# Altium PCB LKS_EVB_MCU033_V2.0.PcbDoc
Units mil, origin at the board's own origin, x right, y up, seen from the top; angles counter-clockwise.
Board outline 2625 x 1560 mil, 2 copper layers (Top Layer, Bottom Layer); 25 components, 32 nets, 123 pads, 18 vias.
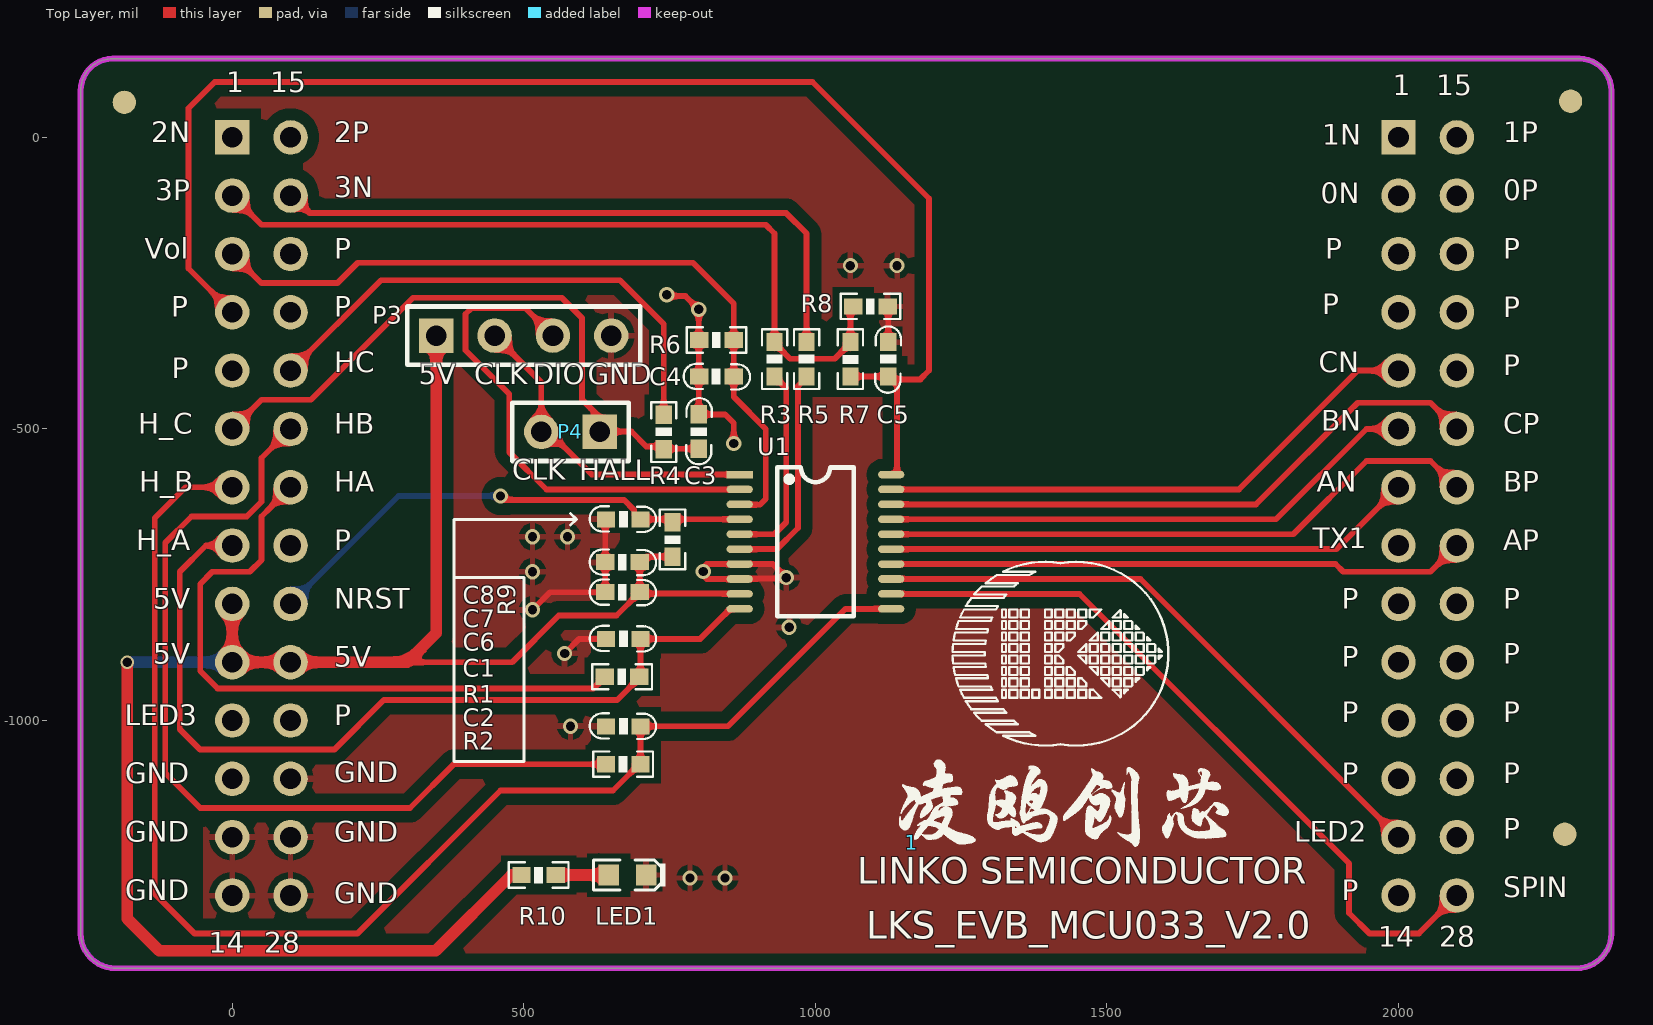
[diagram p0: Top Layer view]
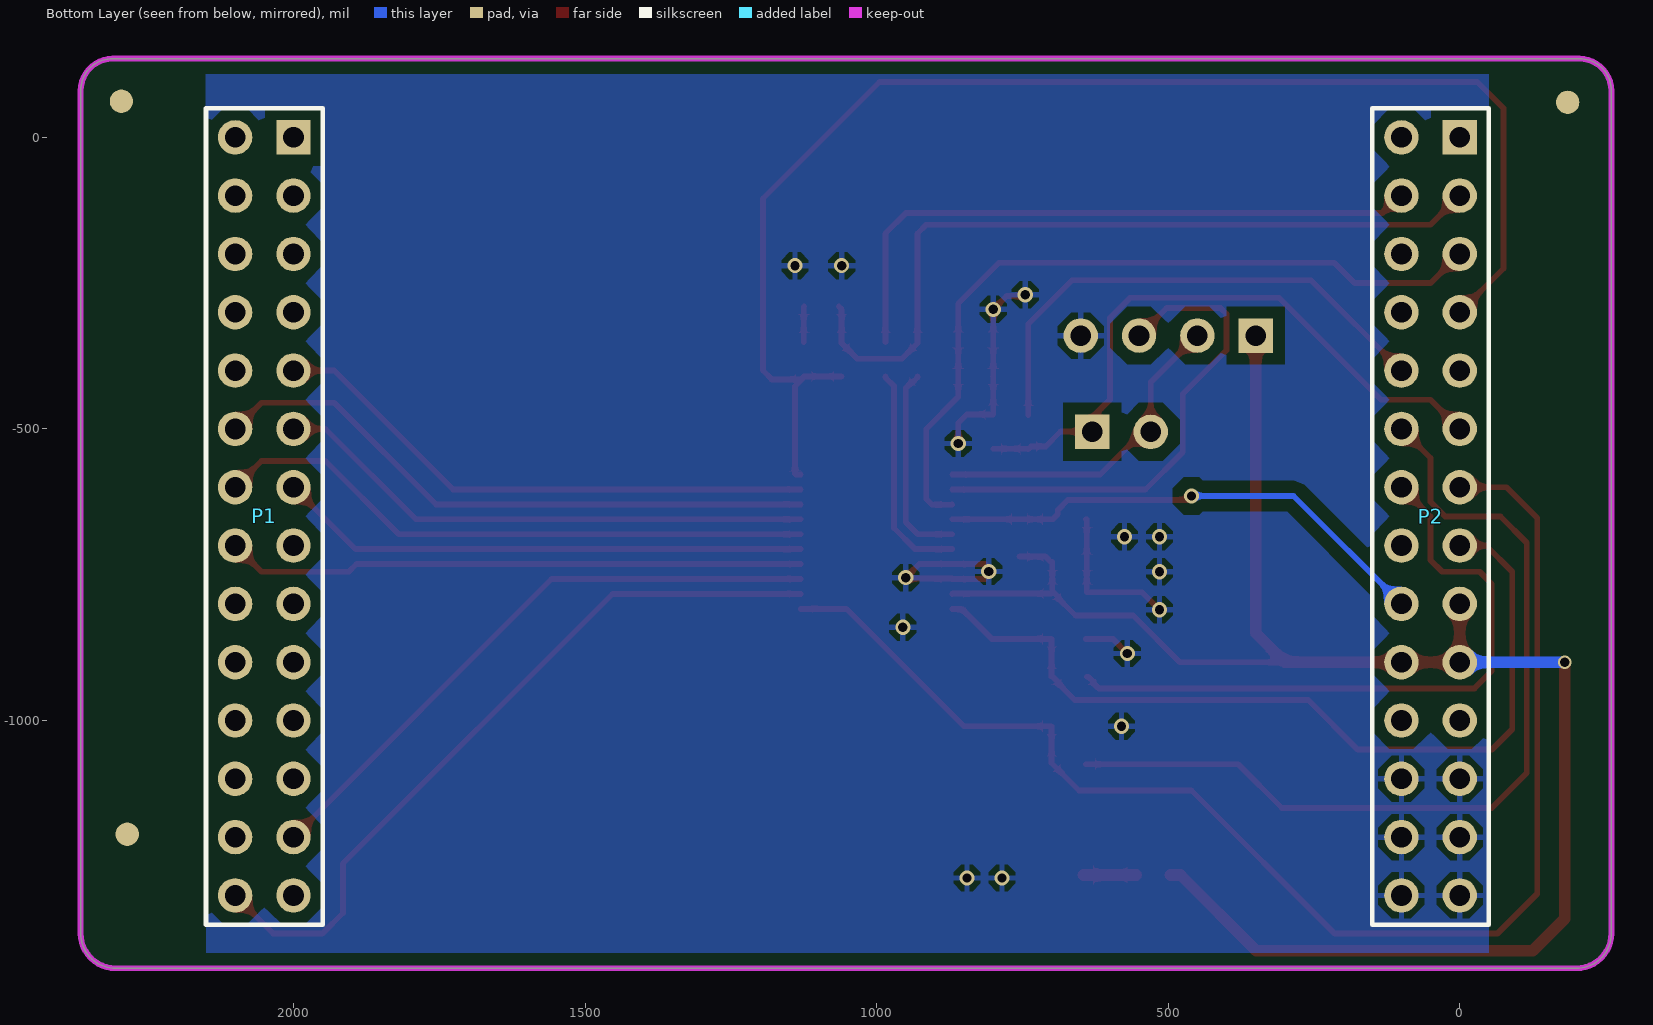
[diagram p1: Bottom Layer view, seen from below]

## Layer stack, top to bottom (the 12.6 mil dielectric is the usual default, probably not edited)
Top Solder: solder mask 0.4, Solder Resist, Dk 3.5
Top Layer: signal copper 1.4
Dielectric 1: dielectric 12.6, FR-4, Dk 4.8
Bottom Layer: signal copper 1.4
Bottom Solder: solder mask 0.4, Solder Resist, Dk 3.5

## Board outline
-260,-1365 ccw(c-200,-1365) -200,-1425 2305,-1425 ccw(c2305,-1365) 2365,-1365 2365,80 ccw(c2310,80) 2310,135 -205,135 ccw(c-205,80) -260,80
cut-out: -2580,-3405 -2570,-3405 -2570,-3395 -2580,-3395

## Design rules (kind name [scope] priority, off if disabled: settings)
Clearance Clearance_2 [InPolygon] p1: gap=20 ignorepadtopadclearanceinfootprint=FALSE
Clearance Clearance_1 [InNet('+5V')] p2: gap=10 ignorepadtopadclearanceinfootprint=FALSE
Clearance [All] p3: gap=7.87 ignorepadtopadclearanceinfootprint=FALSE
ComponentClearance [All] p1: gap=0 collisioncheckmode=3 verticalgap=0 showdistances=FALSE
MinimumSolderMaskSliver [All] p1: minsoldermaskwidth=0
PolygonConnect [All] p1: connectstyle=Relief reliefconductorwidth=10 reliefentries=4 polygonreliefangle="90 Angle" airgapwidth=10
RoutingVias [All] p1: holewidth=28 width=50 viastyle="Through Hole" minholewidth=28 minwidth=50 maxholewidth=28 maxwidth=50
SilkToSilkClearance [All] p1: silktosilkclearance=5
SilkToSolderMaskClearance [IsPad] p1: minsilkscreentomaskgap=5 clearancetoexposedcopper=TRUE
SolderMaskExpansion [All] p1: expansion=4 istentingtop=FALSE
Width [All] p1: maxlimit=100 minlimit=1 preferedwidth=10
26 further rules are at their usual default settings.

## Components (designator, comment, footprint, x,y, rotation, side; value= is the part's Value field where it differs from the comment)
1 "LKS_sign" LKS_LOGO2 1165,-1210 r0 top
C1 "10nF/16V" 0603C 700,-860 r180 top
C2 "10nF/16V" 0603C 700,-1010 r180 top
C3 "10nF/16V" 0603C 800,-534.06 r90 top
C4 "100nF/50V" 0603C 800.94,-410 r0 top
C5 "1nF/50V" 0603C 1125,-350.94 r270 top
C6 "10uF/10V" 0603C 639.76,-780 r0 top
C7 "100nF/50V" 0603C 639.76,-728.43 r0 top
C8 "100nF/50V" 0603C 700,-655 r180 top
LED1 "LED" 0603D 677.82,-1265 r0 top
P1 "Header 14X2A" HDR2X14_CEN 2000,0 r270 bottom
P2 "Header 14X2A" HDR2X14_CEN 0,0 r270 bottom
P3 "Header 4" HDR1X4 350,-340 r0 top
P4 "Header 2" HDR1X2 630,-505 r180 top
R1 "2K" 0603R 638.98,-925 r0 top value=K
R2 "2K" 0603R 640.94,-1075 r0 top value=K
R3 "1K1%" 0603R 930,-350.94 r270 top value=K
R4 "2K" 0603R 740,-475.94 r270 top value=K
R5 "1K1%" 0603R 985,-350.94 r270 top value=K
R6 "1K1%" 0603R 800.94,-347.5 r0 top value=K
R7 "1K1%" 0603R 1060,-410 r90 top value=K
R8 "10R" 0603R 1065,-290 r0 top value=K
R9 "20K1%" 0603R 755,-719.06 r90 top value=K
R10 "3.3K" 0603R 495.94,-1265 r0 top value=330
U1 "LKS033" TSSOP-20 845.16,-561.23 r0 top

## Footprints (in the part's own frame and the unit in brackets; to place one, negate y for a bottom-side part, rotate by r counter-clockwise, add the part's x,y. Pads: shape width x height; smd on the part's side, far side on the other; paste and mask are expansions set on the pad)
0603C [mm]
  rect 0.8x0.7 smd: 1(0,0) 2(1.5,0)
  silkscreen extent -0.68,-0.57 2.21,0.55
0603D [mm]
  rect 0.9x0.9 smd: 1(-0.813,0) 2(0.813,0)
  silkscreen extent -1.47,-0.66 1.65,0.66
0603R [mm]
  rect 0.8x0.7 smd: 1(0,0) 2(1.5,0)
  silkscreen extent -0.55,-0.55 2.05,0.55
HDR1X2 [mm] "Connector; Header; 2 Position"
  rect 1.5x1.5 hole 0.9: 1(0,0)
  round 1.5 hole 0.9: 2(2.54,0)
  silkscreen extent -1.27,-1.27 3.81,1.27
HDR1X4 [mm] "Connector; Header; 4 Position"
  rect 1.5x1.5 hole 0.9: 1(0,0)
  round 1.5 hole 0.9: 2(2.54,0) 3(5.08,0) 4(7.62,0)
  silkscreen extent -1.27,-1.27 8.89,1.27
HDR2X14_CEN [mm] "Connector; Header; 14x2 Position"
  rect 1.5x1.5 hole 0.9: 1(0,0)
  round 1.5 hole 0.9: 2(2.54,0) 3(5.08,0) 4(7.62,0) 5(10.16,0) 6(12.7,0) 7(15.24,0) 8(17.78,0) 9(20.32,0) 10(22.86,0) 11(25.4,0) 12(27.94,0) 13(30.48,0) 14(33.02,0) 15(0,-2.54) 16(2.54,-2.54) 17(5.08,-2.54) 18(7.62,-2.54) 19(10.16,-2.54) 20(12.7,-2.54) 21(15.24,-2.54) 22(17.78,-2.54) 23(20.32,-2.54) 24(22.86,-2.54) 25(25.4,-2.54) 26(27.94,-2.54) 27(30.48,-2.54) 28(33.02,-2.54)
  silkscreen extent -1.27,-3.81 34.29,1.27
LKS_LOGO2 [mil] "LOGO?"
  silkscreen extent 70,167 440,482
TSSOP-20 [mm] "6.50x4.40x1.00 e=0.65（蒜米工坊）"
  rect 1.143x0.33 smd: 1(0.635,-0.432)
  oval 1.143x0.33 smd: 2(0.635,-1.082) 3(0.635,-1.732) 4(0.635,-2.382) 5(0.635,-3.032) 6(0.635,-3.682) 7(0.635,-4.332) 8(0.635,-4.982) 9(0.635,-5.632) 10(0.635,-6.282) 11(7.235,-6.282) 12(7.235,-5.632) 13(7.235,-4.982) 14(7.235,-4.332) 15(7.235,-3.682) 16(7.235,-3.032) 17(7.235,-2.382) 18(7.235,-1.732) 19(7.235,-1.082) 20(7.235,-0.432)
  silkscreen extent 2.27,-6.61 5.6,-0.11, body extent 0.73,-6.55 7.14,-0.05, height 1.03

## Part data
C1 C2 C3: library part CAP, "Capacitor"
C4 C5 C6 C7 C8: library part C, "Capacitor"
LED1: "LED_Light"
P1 P2: "Header, 14-Pin, Dual row"
P3: "Header, 4-Pin"
P4: "Header, 2-Pin"
R1 R2 R3 R4 R5 R6 R7 R8 R9 R10: library part Res, "Resistor"
U1: library part LKS32MC033H6S8, "CHIP--TSSOP20"

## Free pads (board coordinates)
  round 40 all layers, no hole: 2(2295,61.86) 3(2285,-1195) 4(-185,60)

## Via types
v1: diameter 26, hole 16, Top Layer to Bottom Layer, 17 vias
v2: diameter 23.62, hole 15.75, Top Layer to Bottom Layer, 1 vias

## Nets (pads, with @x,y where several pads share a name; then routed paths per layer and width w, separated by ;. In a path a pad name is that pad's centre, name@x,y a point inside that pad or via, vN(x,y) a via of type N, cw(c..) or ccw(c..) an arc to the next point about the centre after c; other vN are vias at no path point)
+5V: C6.2 C7.2 P2.9 P2.10 P2.24 P3.1 R9.1 R10.1 U1.9 | length 3087.2
  Top Layer w10: 300,-900 480,-900 560,-820 658.82,-820 688.07,-790.75 688.07,-788.78 696.85,-780 C6.2 ; R9.1 710.16,-719.06 700.79,-728.43 C7.2 C6.2 ; U1.9 869.59,-782.38 701.2,-782.38 C6.2
  Top Layer w20: v2(-180,-900) -180,-1340 -125,-1395 348.98,-1395 478.98,-1265 R10.1 ; P2.9 P2.10 P2.24 300,-900 350,-850 P3.1
  Bottom Layer w20: v2(-180,-900) P2.10
GND: C1.2 C2.2 C3.2 C4.1 C5.1 C6.1 C7.1 C8.2 LED1.2 P2.12 P2.13 P2.14 P2.26 P2.27 P2.28 P3.4 R6.1 R8.2 U1.7 U1.8 | length 1067
  Top Layer w10: v1(515,-810) 545,-780 C6.1 C7.1 639.76,-655 C8.2 ; v1(570,-885) 595,-860 C1.2 ; v1(745,-270) 747.33,-272.33 777.33,-272.33 v1(800,-295) 800,-409.06 C4.1 800,-410.94 C3.2 845,-475 860,-490 v1(860,-525) ; R8.2 1125,-290.95 C5.1 ; v1@807.82,-751.5 v1(807.82,-744.57) 807.82,-737.63 813.68,-731.77 U1.7 926.77,-731.77 v1(950,-755) 948.21,-756.79 870.73,-756.79 U1.8 813.68,-757.36 v1@807.82,-751.5
  other v1: 785,-1270 845,-1270 580,-1010 955,-840 515,-745 515,-685 575,-685 1060,-220 1140,-220
GND0: P2.16 R5.1 | length 1097.9
  Top Layer w10: P2.16 102.97,-100 132.97,-130 950,-130 985,-165 R5.1
HALL_U: C1.1 P2.8 R1.2 U1.10 | length 1492.5
  Top Layer w10: P2.8 -45,-700 -90,-745 -90,-1015 -55,-1050 175,-1050 260,-965 660,-965 689.25,-935.75 689.25,-933.78 R1.2 700,-925 C1.1 802.7,-860 854.15,-808.54 U1.10
HALL_V: C2.1 P2.7 R2.2 U1.11 | length 2357.4
  Top Layer w10: P2.7 -80,-600 -132.87,-652.87 -132.87,-1297.13 -65,-1365 215,-1365 460,-1120 653.03,-1120 700,-1073.03 C2.1 850,-1010 1051.46,-808.54 U1.11
HALL_W: C3.1 P2.6 P4.1 R4.2 | length 1083.3
  Top Layer w10: P2.6 50,-450 135,-450 310,-275 565,-275 600,-310 600,-450 630,-480 654.53,-504.53 684.53,-504.53 710,-530 735,-530 R4.2 740.94,-534.06 C3.1
HU: P2.21 R1.1 | length 1132.6
  Top Layer w10: P2.21 66.99,-633.01 66.99,-633.29 50,-650.28 50,-725 30,-745 -34.14,-745 -55,-765.86 -55,-915 -25,-945 618.98,-945 628.23,-935.75 628.23,-933.78 637.01,-925 R1.1
HV: P2.20 R2.1 | length 1546.6
  Top Layer w10: P2.20 50,-550 50,-625 25,-650 -70,-650 -115,-695 -115,-1090 -55,-1150 305,-1150 380,-1075 R2.1
HW: P2.19 R4.1 | length 891.2
  Top Layer w10: P2.19 255,-245 665,-245 740,-320 R4.1
LED2: P1.13 U1.13 | length 1053.3
  Top Layer w10: U1.13 1557.36,-757.36 P1.13
NetLED1_1: LED1.1 R10.2 | length 90.8
  Top Layer w20: R10.2 LED1.1
NRST: C8.1 P2.23 R9.2 U1.4 | length 867.4
  Top Layer w10: v1(460,-615) 464.33,-615 471.02,-621.69 671.69,-621.69 689.25,-639.25 689.25,-646.22 698.03,-655 755,-655 U1.4
  Bottom Layer w10: P2.23 285,-615 v1(460,-615)
OC: C5.2 P2.4 R7.1 U1.20 | length 2374.5
  Top Layer w10: P2.4 -75,-225 -75,50 -30,95 995,95 1195,-105 1195,-400 1180,-415 1130,-415 C5.2 ; R7.1 C5.2 ; U1.20 1138.62,-578.23 1140,-576.85 1140,-426.97 1125,-411.97 C5.2
OPA1_IN: R5.2 U1.6 | length 381.3
  Top Layer w10: U1.6 933.82,-706.18 970,-670 970,-426.61 975.86,-420.75 976.22,-420.75 985,-411.97 R5.2
OPA1_IP: R3.2 U1.5 | length 347.8
  Top Layer w10: U1.5 929.41,-680.59 950,-660 950,-430 940.75,-420.75 938.78,-420.75 930,-411.97 R3.2
PGND: P2.2 R3.1 R7.2 R8.1 | length 1361.9
  Top Layer w10: P2.2 50,-150 915,-150 930,-165 R3.1 930,-352.91 956.65,-379.57 1033.35,-379.57 1060,-352.91 R7.2 1060,-295 R8.1
PGND0: P1.2
PGND1: P1.1
PGND2: P2.1
SPin: P1.28 U1.12 | length 1292.8
  Top Layer w10: U1.12 1452.95,-782.95 1915,-1245 1915,-1330 1950,-1365 2035,-1365 P1.28
  Bottom Layer w10: P1.28 P1.28@2100,-1295
SWCLK: P3.2 P4.2 U1.1 | length 560.8
  Top Layer w10: P3.2 530,-420 530,-491.61 616.61,-578.23 U1.1
SWDIO: P3.3 U1.2 | length 863.4
  Top Layer w10: P3.3 502.87,-292.87 410,-292.87 400,-302.87 400,-365 475,-440 475,-540 538.82,-603.82 U1.2
UN: P1.7 U1.15 | length 914
  Top Layer w10: U1.15 1893.82,-706.18 P1.7
UP: P1.22 U1.14 | length 994.1
  Top Layer w10: U1.14 1891.77,-731.77 1905,-745 2055,-745 P1.22
UP-: P2.15
VN: P1.6 U1.17 | length 934.2
  Top Layer w10: U1.17 1790,-655 1945,-500 P1.6
Vol_ADC: C4.2 P2.3 R6.2 U1.3 | length 1331.2
  Top Layer w10: P2.3 50,-250 180,-250 215,-215 790,-215 860,-285 R6.2 C4.2 860,-445 915,-500 915,-620 905,-630 870.73,-629.98 U1.3
VP: P1.21 U1.16 | length 1040.7
  Top Layer w10: U1.16 1819.41,-680.59 1945,-555 2055,-555 P1.21
VP-: P1.15
WN: P1.5 U1.19 | length 954.4
  Top Layer w10: U1.19 1726.18,-603.82 1930,-400 P1.5
WP: P1.20 U1.18 | length 1060.9
  Top Layer w10: U1.18 1755.59,-629.41 1930,-455 2055,-455 P1.20
WP-: P1.16
pads on no net: P1.3 P1.4 P1.8 P1.9 P1.10 P1.11 P1.12 P1.14 P1.17 P1.18 P1.19 P1.23 P1.24 P1.25 P1.26 P1.27 P2.5 P2.11 P2.17 P2.18 P2.22 P2.25

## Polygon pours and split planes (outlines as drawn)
GND on Bottom Layer "GND_L02_P000" (solid, remove dead copper, pour order 0): -50,128.77 -50,-1425 2150,-1425 2150,134.58
GND on Top Layer "GND_L01_P005" (solid, remove dead copper, pour order 5): -50,-1425 2150,-1425 2150,135 -50,135

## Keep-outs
Keep-Out Layer:
  the board outline again, w10

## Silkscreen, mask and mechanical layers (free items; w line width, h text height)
Top Overlay:
  drawing of 16 lines, arcs and shapes, not listed
  text "2N" at -138.73,-20 h60
  text "2P" at 175,-20 h60
  text "1P" at 2180,-20 h60
  text "1N" at 1869.55,-25 h60
  text "3N" at 174.94,-115 h60
  text "3P" at -131.62,-120 h60
  text "0P" at 2179.94,-120 h60
  text "0N" at 1866.83,-125 h60
  text "Vol" at -149.61,-220 h60
  text "P" at 175,-220 h60
  text "P" at 1874.54,-220 h60
  text "P" at 2180,-220 h60
  text "P" at 1869.27,-315 h60
  text "P" at -105,-320 h60
  text "P" at 175,-320 h60
  text "P" at 2180,-320.67 h60
  text "HC" at 175,-415 h60
  text "CN" at 1863.33,-415 h60
  text "P" at 2180,-420 h60
  text "P" at -103.71,-425 h60
  text "5V" at 320,-435 h60
  text "CLK" at 415,-435 h60
  text "DIO" at 515,-435 h60
  text "GND" at 610,-435 h60
  text "BN" at 1867.44,-515 h60
  text "H_C" at -161.26,-520 h60
  text "HB" at 175,-520 h60
  text "CP" at 2180,-520 h60
  text "CLK" at 480.06,-599.45 h60
  text "HALL" at 595.06,-600 h60
  text "H_B" at -159.43,-620 h60
  text "HA" at 175,-620 h60
  text "AN" at 1860,-620 h60
  text "BP" at 2180,-620 h60
  text "TX1" at 1852.62,-716.98 h60
  text "H_A" at -164.7,-720 h60
  text "P" at 175,-720 h60
  text "AP" at 2179.94,-720 h60
  text "5V" at -135.4,-820 h60
  text "NRST" at 175,-820 h60
  text "P" at 1902.51,-820 h60
  text "P" at 2180,-820 h60
  text "5V" at -135.4,-915 h60
  text "P" at 2180,-915 h60
  text "5V" at 174.94,-920 h60
  text "P" at 1902.51,-920 h60
  text "P" at 1902.51,-1015 h60
  text "P" at 2180,-1015 h60
  text "LED3" at -183.91,-1020 h60
  text "P" at 175,-1020 h60
  text "GND" at 175,-1118.3 h60
  text "GND" at -183.07,-1120 h60
  text "P" at 1902.51,-1120 h60
  text "P" at 2179.94,-1120 h60
  text "P" at 2180,-1215 h60
  text "GND" at -183.07,-1220 h60
  text "GND" at 175,-1220 h60
  text "LED2" at 1821.32,-1220 h60
  text "SPIN" at 2180,-1315 h60
  text "GND" at -183.07,-1320 h60
  text "P" at 1902.51,-1320 h60
  text "GND" at 175,-1325 h60
  text "LKS_EVB_MCU033_V2.0" at 1087.5,-1390 h80
Top Solder:
  circle w78: c2285,-1195 r17
  circle w78: c-185,60 r17
  circle w78: c2295,61.86 r17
